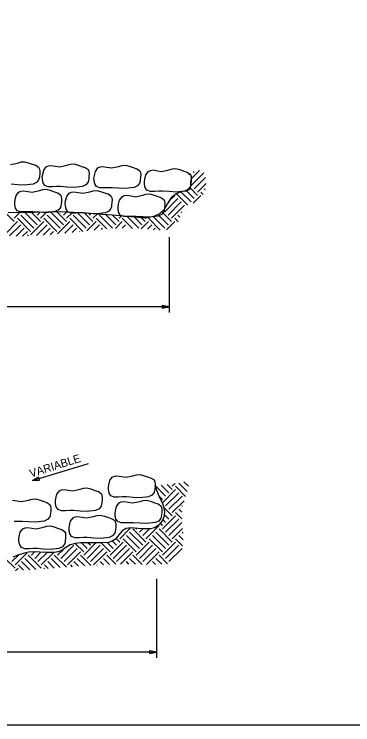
# Model space of a CAD drawing. Extents: x -439.1 to -407.9, y -458.1 to -436.2.
# Drawn here: x -424.66 to -418.4, y -458.05 to -444.91 of the extents above; entities that cross this region are included whole.
import ezdxf

# ---------------------------------------------------------------- set-up
doc = ezdxf.new("R2010")
doc.units = 0
doc.layers.add('Draft_Named_Boundary', color=7, linetype='Continuous')
doc.layers.add('Level 4', color=7, linetype='Continuous')

msp = doc.modelspace()

# ---------------------------------------------------------------- linework, layer by layer
at = {"layer": 'Draft_Named_Boundary'}
msp.add_lwpolyline([(-439.109, -458.051), (-407.859, -458.051), (-407.859, -437.676), (-439.109, -437.676)], close=True, dxfattribs=at)
at = {"layer": 'Level 4'}
for p, q in [((-421.415, -447.871), (-421.429, -447.856)), ((-421.389, -448.078), (-421.155, -447.844)), ((-421.38, -447.947), (-421.231, -447.798)), ((-421.329, -447.835), (-421.348, -447.816)), ((-421.329, -448.138), (-421.121, -447.931)), ((-421.268, -448.26), (-421.405, -448.123)), ((-421.268, -448.199), (-421.111, -448.042)), ((-421.799, -448.366), (-421.692, -448.26)), ((-421.45, -448.441), (-421.66, -448.231)), ((-421.389, -448.381), (-421.578, -448.193)), ((-421.329, -448.32), (-421.474, -448.174)), ((-421.352, -448.404), (-421.208, -448.26)), ((-421.166, -448.241), (-421.208, -448.199)), ((-421.129, -448.156), (-421.147, -448.138)), ((-421.874, -448.563), (-421.632, -448.32)), ((-421.814, -448.623), (-421.571, -448.381)), ((-421.753, -448.684), (-421.511, -448.441)), ((-421.508, -448.505), (-421.511, -448.502)), ((-424.663, -448.744), (-424.824, -448.583)), ((-424.663, -448.684), (-424.563, -448.584)), ((-424.299, -448.866), (-424.541, -448.623)), ((-424.238, -448.805), (-424.462, -448.581)), ((-424.178, -448.744), (-424.345, -448.577)), ((-424.238, -448.623), (-424.185, -448.57)), ((-424.178, -448.684), (-424.06, -448.566)), ((-423.814, -448.866), (-424.056, -448.623)), ((-423.753, -448.805), (-423.994, -448.564)), ((-423.693, -448.744), (-423.874, -448.563)), ((-423.753, -448.623), (-423.698, -448.568)), ((-423.693, -448.684), (-423.583, -448.574)), ((-423.329, -448.866), (-423.571, -448.623)), ((-423.268, -448.805), (-423.495, -448.578)), ((-423.208, -448.744), (-423.365, -448.587)), ((-423.268, -448.623), (-423.242, -448.596)), ((-423.208, -448.684), (-423.129, -448.605)), ((-422.844, -448.866), (-423.087, -448.623)), ((-422.783, -448.805), (-422.974, -448.615)), ((-422.723, -448.744), (-422.844, -448.623)), ((-422.723, -448.684), (-422.677, -448.638)), ((-422.359, -448.866), (-422.578, -448.647)), ((-421.874, -448.866), (-422.09, -448.65)), ((-421.814, -448.805), (-422.003, -448.615)), ((-421.753, -448.744), (-421.932, -448.565)), ((-421.595, -448.66), (-421.632, -448.623)), ((-421.56, -448.574), (-421.571, -448.563)), ((-424.844, -448.987), (-424.602, -448.744)), ((-424.359, -448.926), (-424.602, -448.684)), ((-424.359, -448.987), (-424.117, -448.744)), ((-423.875, -448.926), (-424.117, -448.684)), ((-423.862, -448.974), (-423.632, -448.744)), ((-423.391, -448.925), (-423.632, -448.684)), ((-423.319, -448.916), (-423.147, -448.744)), ((-422.951, -448.88), (-423.147, -448.684)), ((-422.79, -448.873), (-422.662, -448.744)), ((-422.474, -448.872), (-422.662, -448.684)), ((-422.299, -448.805), (-422.439, -448.664)), ((-422.312, -448.879), (-422.177, -448.744)), ((-422.238, -448.744), (-422.308, -448.675)), ((-422.238, -448.684), (-422.227, -448.673)), ((-421.959, -448.902), (-422.177, -448.684)), ((-421.843, -448.895), (-421.692, -448.744)), ((-421.628, -448.748), (-421.692, -448.684)), ((-424.748, -449.011), (-424.541, -448.805)), ((-424.627, -449.012), (-424.481, -448.866)), ((-424.253, -449.001), (-424.056, -448.805)), ((-424.125, -448.995), (-423.996, -448.866)), ((-423.727, -448.961), (-423.571, -448.805)), ((-423.593, -448.948), (-423.511, -448.866)), ((-423.183, -448.902), (-423.087, -448.805)), ((-423.049, -448.889), (-423.026, -448.866)), ((-422.664, -448.868), (-422.602, -448.805)), ((-422.544, -448.869), (-422.541, -448.866)), ((-422.198, -448.887), (-422.117, -448.805)), ((-422.087, -448.896), (-422.056, -448.866)), ((-424.507, -449.014), (-424.42, -448.926)), ((-424.398, -449.009), (-424.42, -448.987)), ((-423.996, -448.987), (-423.935, -448.926)), ((-423.457, -448.933), (-423.45, -448.926)), ((-421.795, -449.03), (-421.795, -450.423)), ((-421.795, -450.321), (-435.852, -450.321)), ((-424.324, -453.535), (-423.287, -453.219)), ((-421.86, -453.822), (-422.054, -453.628)), ((-421.799, -453.762), (-421.942, -453.619)), ((-421.739, -453.701), (-421.832, -453.608)), ((-421.739, -453.64), (-421.684, -453.586)), ((-421.492, -453.826), (-421.678, -453.64)), ((-421.461, -453.737), (-421.617, -453.58)), ((-421.437, -453.639), (-421.521, -453.555)), ((-421.921, -453.943), (-421.678, -453.701)), ((-421.86, -454.004), (-421.617, -453.762)), ((-421.921, -453.883), (-421.986, -453.818)), ((-421.799, -454.065), (-421.557, -453.822)), ((-421.739, -454.125), (-421.519, -453.906)), ((-421.739, -454.186), (-421.904, -454.021)), ((-421.546, -454.015), (-421.557, -454.004)), ((-421.799, -454.246), (-421.891, -454.155)), ((-421.562, -454.241), (-421.678, -454.125)), ((-421.562, -454.12), (-421.617, -454.065)), ((-421.921, -454.428), (-421.678, -454.186)), ((-421.86, -454.307), (-421.913, -454.254)), ((-421.86, -454.489), (-421.617, -454.246)), ((-422.709, -454.61), (-422.514, -454.415)), ((-422.224, -454.671), (-422.466, -454.428)), ((-422.405, -454.428), (-422.395, -454.418)), ((-422.345, -454.489), (-422.282, -454.427)), ((-422.284, -454.55), (-422.161, -454.426)), ((-422.224, -454.61), (-421.981, -454.368)), ((-421.739, -454.671), (-421.981, -454.428)), ((-421.921, -454.368), (-421.965, -454.324)), ((-421.799, -454.55), (-421.558, -454.308)), ((-421.739, -454.61), (-421.546, -454.418)), ((-422.345, -454.792), (-422.587, -454.55)), ((-422.284, -454.731), (-422.527, -454.489)), ((-421.86, -454.792), (-422.102, -454.55)), ((-421.799, -454.731), (-422.042, -454.489)), ((-421.535, -454.632), (-421.617, -454.55)), ((-421.536, -454.51), (-421.557, -454.489)), ((-423.375, -454.853), (-423.532, -454.696)), ((-423.315, -454.792), (-423.419, -454.688)), ((-423.375, -454.913), (-423.15, -454.688)), ((-423.254, -454.731), (-423.298, -454.687)), ((-422.89, -454.853), (-423.056, -454.687)), ((-422.83, -454.792), (-422.943, -454.679)), ((-422.89, -454.913), (-422.648, -454.671)), ((-422.769, -454.731), (-422.853, -454.648)), ((-422.709, -454.671), (-422.776, -454.603)), ((-422.405, -454.853), (-422.648, -454.61)), ((-422.405, -454.913), (-422.163, -454.671)), ((-421.921, -454.853), (-422.163, -454.61)), ((-421.921, -454.913), (-421.678, -454.671)), ((-421.545, -454.743), (-421.678, -454.61)), ((-423.86, -454.913), (-423.76, -454.813)), ((-423.8, -454.974), (-423.557, -454.731)), ((-423.739, -455.034), (-423.496, -454.792)), ((-423.315, -454.974), (-423.072, -454.731)), ((-423.254, -455.034), (-423.012, -454.792)), ((-422.83, -454.974), (-422.587, -454.731)), ((-422.769, -455.034), (-422.527, -454.792)), ((-422.345, -454.974), (-422.102, -454.731)), ((-422.284, -455.034), (-422.042, -454.792)), ((-421.86, -454.974), (-421.617, -454.731)), ((-421.799, -455.034), (-421.557, -454.792)), ((-424.709, -455.034), (-424.585, -454.911)), ((-424.648, -455.095), (-424.424, -454.87)), ((-424.163, -455.156), (-424.406, -454.913)), ((-424.345, -454.913), (-424.286, -454.854)), ((-424.284, -454.974), (-424.17, -454.859)), ((-424.224, -455.034), (-424.052, -454.863)), ((-424.163, -455.095), (-423.933, -454.865)), ((-423.698, -455.136), (-423.921, -454.913)), ((-423.86, -454.853), (-423.864, -454.849)), ((-423.678, -455.095), (-423.436, -454.853)), ((-423.244, -455.105), (-423.436, -454.913)), ((-423.193, -455.095), (-422.951, -454.853)), ((-422.782, -455.082), (-422.951, -454.913)), ((-422.696, -455.083), (-422.466, -454.853)), ((-422.296, -455.084), (-422.466, -454.913)), ((-422.213, -455.084), (-421.981, -454.853)), ((-421.823, -455.071), (-421.981, -454.913)), ((-424.648, -455.156), (-424.83, -454.974)), ((-424.377, -455.185), (-424.527, -455.034)), ((-424.264, -455.177), (-424.466, -454.974)), ((-423.924, -455.152), (-424.042, -455.034)), ((-423.811, -455.144), (-423.981, -454.974)), ((-423.471, -455.12), (-423.557, -455.034)), ((-423.358, -455.112), (-423.496, -454.974)), ((-423.013, -455.094), (-423.072, -455.034)), ((-422.897, -455.088), (-423.012, -454.974)), ((-422.539, -455.083), (-422.587, -455.034)), ((-422.417, -455.083), (-422.527, -454.974)), ((-422.049, -455.088), (-422.102, -455.034)), ((-421.932, -455.083), (-422.042, -454.974)), ((-424.637, -455.205), (-424.588, -455.156)), ((-424.489, -455.193), (-424.588, -455.095)), ((-424.113, -455.166), (-424.103, -455.156)), ((-424.037, -455.16), (-424.103, -455.095)), ((-423.585, -455.128), (-423.618, -455.095)), ((-423.128, -455.1), (-423.133, -455.095)), ((-422.03, -455.352), (-422.03, -456.812)), ((-422.03, -456.709), (-435.329, -456.709))]:
    msp.add_line(p, q, dxfattribs=at)
for points in [[(-424.733, -447.689), (-424.602, -447.661), (-424.537, -447.642), (-424.473, -447.637), (-424.403, -447.655), (-424.329, -447.683), (-424.262, -447.703), (-424.211, -447.738), (-424.196, -447.772), (-424.191, -447.811), (-424.192, -447.86), (-424.197, -447.909), (-424.202, -447.942), (-424.211, -447.972), (-424.251, -448.022), (-424.314, -448.052), (-424.47, -448.07), (-424.6, -448.063), (-424.72, -448.054)], [(-421.548, -448.181), (-421.473, -448.176), (-421.414, -448.145), (-421.4, -448.117), (-421.395, -448.082), (-421.391, -448), (-421.377, -447.939), (-421.385, -447.89), (-421.41, -447.872), (-421.442, -447.862)], [(-421.548, -448.181), (-421.664, -448.231), (-421.76, -448.308), (-421.825, -448.413), (-421.888, -448.521), (-421.973, -448.598), (-422.079, -448.648), (-422.198, -448.673), (-422.32, -448.675), (-422.567, -448.648), (-422.845, -448.623), (-423.119, -448.606), (-423.459, -448.58), (-423.799, -448.563), (-424.288, -448.575), (-424.776, -448.584)], [(-422.063, -453.628), (-422.025, -453.722), (-421.986, -453.816), (-421.918, -453.961), (-421.892, -454.035), (-421.882, -454.113), (-421.89, -454.187), (-421.914, -454.259), (-421.953, -454.323), (-422.004, -454.374), (-422.067, -454.409), (-422.139, -454.426), (-422.3, -454.427), (-422.503, -454.411), (-422.593, -454.422), (-422.667, -454.461), (-422.727, -454.539), (-422.789, -454.618), (-422.847, -454.656), (-422.916, -454.677), (-423.068, -454.688), (-423.253, -454.687), (-423.434, -454.688), (-423.533, -454.696), (-423.626, -454.723), (-423.705, -454.775), (-423.783, -454.828), (-423.851, -454.853), (-423.925, -454.865), (-424.08, -454.863), (-424.294, -454.854), (-424.397, -454.86), (-424.498, -454.88), (-424.594, -454.914), (-424.69, -454.95)], [(-424.694, -453.898), (-424.611, -453.91), (-424.53, -453.924), (-424.398, -453.896), (-424.333, -453.878), (-424.27, -453.872), (-424.199, -453.89), (-424.125, -453.918), (-424.058, -453.939), (-424.007, -453.974), (-423.993, -454.007), (-423.987, -454.046), (-423.988, -454.095), (-423.994, -454.144), (-423.999, -454.177), (-424.007, -454.207), (-424.047, -454.257), (-424.111, -454.287), (-424.267, -454.305), (-424.397, -454.298), (-424.517, -454.289), (-424.588, -454.289), (-424.664, -454.292)]]:
    msp.add_lwpolyline(points, dxfattribs=at)
for points in [[(-424.135, -447.873), (-424.117, -447.794), (-424.07, -447.732), (-424.029, -447.712), (-423.984, -447.705), (-423.901, -447.718), (-423.82, -447.732), (-423.689, -447.704), (-423.624, -447.685), (-423.56, -447.679), (-423.49, -447.697), (-423.416, -447.725), (-423.349, -447.746), (-423.297, -447.781), (-423.283, -447.815), (-423.278, -447.853), (-423.279, -447.903), (-423.284, -447.952), (-423.289, -447.984), (-423.297, -448.014), (-423.337, -448.064), (-423.401, -448.094), (-423.557, -448.113), (-423.687, -448.106), (-423.807, -448.096), (-423.878, -448.096), (-423.955, -448.1), (-424.032, -448.1), (-424.096, -448.077), (-424.128, -448.028), (-424.142, -447.965), (-424.143, -447.918), (-424.135, -447.873)], [(-423.18, -447.894), (-423.161, -447.816), (-423.114, -447.753), (-423.074, -447.733), (-423.029, -447.727), (-422.946, -447.739), (-422.864, -447.753), (-422.733, -447.725), (-422.668, -447.706), (-422.605, -447.7), (-422.534, -447.718), (-422.46, -447.746), (-422.393, -447.767), (-422.342, -447.802), (-422.327, -447.836), (-422.322, -447.874), (-422.323, -447.924), (-422.329, -447.973), (-422.333, -448.005), (-422.342, -448.035), (-422.382, -448.085), (-422.445, -448.115), (-422.601, -448.134), (-422.731, -448.127), (-422.851, -448.118), (-422.923, -448.118), (-422.999, -448.121), (-423.076, -448.121), (-423.14, -448.098), (-423.172, -448.049), (-423.186, -447.986), (-423.187, -447.939), (-423.18, -447.894)], [(-422.245, -447.958), (-422.227, -447.879), (-422.18, -447.817), (-422.139, -447.797), (-422.094, -447.79), (-422.011, -447.803), (-421.93, -447.817), (-421.798, -447.789), (-421.734, -447.77), (-421.67, -447.764), (-421.6, -447.782), (-421.526, -447.81), (-421.459, -447.831), (-421.407, -447.866), (-421.393, -447.899), (-421.388, -447.938), (-421.389, -447.988), (-421.394, -448.037), (-421.399, -448.069), (-421.407, -448.099), (-421.447, -448.149), (-421.511, -448.179), (-421.667, -448.198), (-421.797, -448.19), (-421.917, -448.181), (-421.988, -448.181), (-422.065, -448.185), (-422.142, -448.185), (-422.206, -448.162), (-422.238, -448.113), (-422.252, -448.05), (-422.253, -448.003), (-422.245, -447.958)], [(-424.645, -448.34), (-424.627, -448.261), (-424.579, -448.199), (-424.539, -448.179), (-424.494, -448.173), (-424.411, -448.185), (-424.33, -448.199), (-424.198, -448.171), (-424.133, -448.152), (-424.07, -448.146), (-423.999, -448.164), (-423.925, -448.192), (-423.858, -448.213), (-423.807, -448.248), (-423.793, -448.282), (-423.787, -448.32), (-423.788, -448.37), (-423.794, -448.419), (-423.799, -448.451), (-423.807, -448.481), (-423.847, -448.531), (-423.91, -448.561), (-424.067, -448.58), (-424.197, -448.573), (-424.316, -448.564), (-424.388, -448.564), (-424.464, -448.567), (-424.541, -448.567), (-424.606, -448.544), (-424.638, -448.495), (-424.652, -448.432), (-424.652, -448.385), (-424.645, -448.34)], [(-423.711, -448.361), (-423.692, -448.283), (-423.645, -448.22), (-423.604, -448.201), (-423.559, -448.194), (-423.477, -448.206), (-423.395, -448.22), (-423.264, -448.192), (-423.199, -448.173), (-423.136, -448.167), (-423.065, -448.186), (-422.991, -448.213), (-422.924, -448.234), (-422.873, -448.269), (-422.858, -448.303), (-422.853, -448.342), (-422.854, -448.391), (-422.86, -448.44), (-422.864, -448.472), (-422.873, -448.503), (-422.913, -448.553), (-422.976, -448.583), (-423.132, -448.601), (-423.262, -448.594), (-423.382, -448.585), (-423.454, -448.585), (-423.53, -448.588), (-423.607, -448.588), (-423.671, -448.565), (-423.703, -448.516), (-423.717, -448.453), (-423.718, -448.406), (-423.711, -448.361)], [(-422.734, -448.425), (-422.715, -448.346), (-422.668, -448.284), (-422.628, -448.264), (-422.583, -448.257), (-422.5, -448.27), (-422.418, -448.284), (-422.287, -448.256), (-422.222, -448.237), (-422.159, -448.231), (-422.088, -448.249), (-422.014, -448.277), (-421.947, -448.298), (-421.896, -448.333), (-421.881, -448.367), (-421.876, -448.405), (-421.877, -448.455), (-421.883, -448.504), (-421.887, -448.536), (-421.896, -448.566), (-421.936, -448.616), (-421.999, -448.646), (-422.155, -448.665), (-422.285, -448.658), (-422.405, -448.648), (-422.477, -448.649), (-422.553, -448.652), (-422.63, -448.652), (-422.694, -448.629), (-422.726, -448.58), (-422.74, -448.517), (-422.741, -448.47), (-422.734, -448.425)], [(-421.922, -450.347), (-421.795, -450.321), (-421.922, -450.294)], [(-424.211, -453.473), (-424.324, -453.535), (-424.195, -453.524)], [(-424.211, -453.473), (-424.324, -453.535), (-424.195, -453.524)], [(-422.913, -453.614), (-422.894, -453.535), (-422.847, -453.473), (-422.807, -453.453), (-422.762, -453.446), (-422.679, -453.459), (-422.597, -453.473), (-422.466, -453.445), (-422.401, -453.426), (-422.338, -453.42), (-422.267, -453.438), (-422.193, -453.466), (-422.126, -453.487), (-422.075, -453.522), (-422.06, -453.555), (-422.055, -453.594), (-422.056, -453.644), (-422.062, -453.693), (-422.066, -453.725), (-422.075, -453.755), (-422.115, -453.805), (-422.178, -453.835), (-422.334, -453.854), (-422.464, -453.846), (-422.584, -453.837), (-422.656, -453.837), (-422.732, -453.841), (-422.809, -453.841), (-422.873, -453.818), (-422.905, -453.769), (-422.919, -453.706), (-422.92, -453.659), (-422.913, -453.614)], [(-423.891, -453.865), (-423.873, -453.786), (-423.826, -453.724), (-423.785, -453.704), (-423.74, -453.697), (-423.657, -453.71), (-423.576, -453.724), (-423.445, -453.696), (-423.38, -453.677), (-423.316, -453.671), (-423.246, -453.689), (-423.172, -453.717), (-423.105, -453.738), (-423.054, -453.773), (-423.039, -453.806), (-423.034, -453.845), (-423.035, -453.895), (-423.04, -453.944), (-423.045, -453.976), (-423.054, -454.006), (-423.093, -454.056), (-423.157, -454.086), (-423.313, -454.105), (-423.443, -454.097), (-423.563, -454.088), (-423.635, -454.088), (-423.711, -454.092), (-423.788, -454.092), (-423.852, -454.069), (-423.884, -454.02), (-423.898, -453.957), (-423.899, -453.91), (-423.891, -453.865)], [(-422.787, -454.091), (-422.769, -454.012), (-422.722, -453.949), (-422.681, -453.93), (-422.636, -453.923), (-422.553, -453.935), (-422.472, -453.949), (-422.34, -453.921), (-422.275, -453.903), (-422.212, -453.897), (-422.142, -453.915), (-422.068, -453.943), (-422, -453.964), (-421.949, -453.999), (-421.935, -454.032), (-421.93, -454.071), (-421.931, -454.121), (-421.936, -454.17), (-421.941, -454.202), (-421.949, -454.232), (-421.989, -454.282), (-422.053, -454.312), (-422.209, -454.331), (-422.339, -454.323), (-422.459, -454.314), (-422.53, -454.314), (-422.607, -454.317), (-422.684, -454.317), (-422.748, -454.294), (-422.78, -454.245), (-422.794, -454.183), (-422.795, -454.136), (-422.787, -454.091)], [(-423.64, -454.367), (-423.622, -454.288), (-423.575, -454.225), (-423.534, -454.206), (-423.489, -454.199), (-423.407, -454.212), (-423.325, -454.225), (-423.194, -454.198), (-423.129, -454.179), (-423.065, -454.173), (-422.995, -454.191), (-422.921, -454.219), (-422.854, -454.24), (-422.803, -454.275), (-422.788, -454.308), (-422.783, -454.347), (-422.784, -454.397), (-422.789, -454.446), (-422.794, -454.478), (-422.803, -454.508), (-422.843, -454.558), (-422.906, -454.588), (-423.062, -454.607), (-423.192, -454.599), (-423.312, -454.59), (-423.384, -454.59), (-423.46, -454.593), (-423.537, -454.593), (-423.601, -454.57), (-423.633, -454.521), (-423.647, -454.459), (-423.648, -454.412), (-423.64, -454.367)], [(-424.569, -454.568), (-424.551, -454.489), (-424.503, -454.426), (-424.463, -454.407), (-424.418, -454.4), (-424.335, -454.412), (-424.254, -454.426), (-424.122, -454.398), (-424.057, -454.379), (-423.994, -454.374), (-423.923, -454.392), (-423.849, -454.42), (-423.782, -454.441), (-423.731, -454.475), (-423.717, -454.509), (-423.711, -454.548), (-423.712, -454.597), (-423.718, -454.646), (-423.723, -454.679), (-423.731, -454.709), (-423.771, -454.759), (-423.835, -454.789), (-423.991, -454.807), (-424.121, -454.8), (-424.24, -454.791), (-424.312, -454.791), (-424.388, -454.794), (-424.465, -454.794), (-424.53, -454.771), (-424.562, -454.722), (-424.576, -454.66), (-424.576, -454.613), (-424.569, -454.568)], [(-422.156, -456.735), (-422.03, -456.709), (-422.156, -456.683)]]:
    msp.add_lwpolyline(points, close=True, dxfattribs=at)

# ---------------------------------------------------------------- texts
msp.add_text('VARIABLE', height=0.15, rotation=17.5271, dxfattribs=at).set_placement((-424.354, -453.48))

doc.saveas('drawing.dxf')
